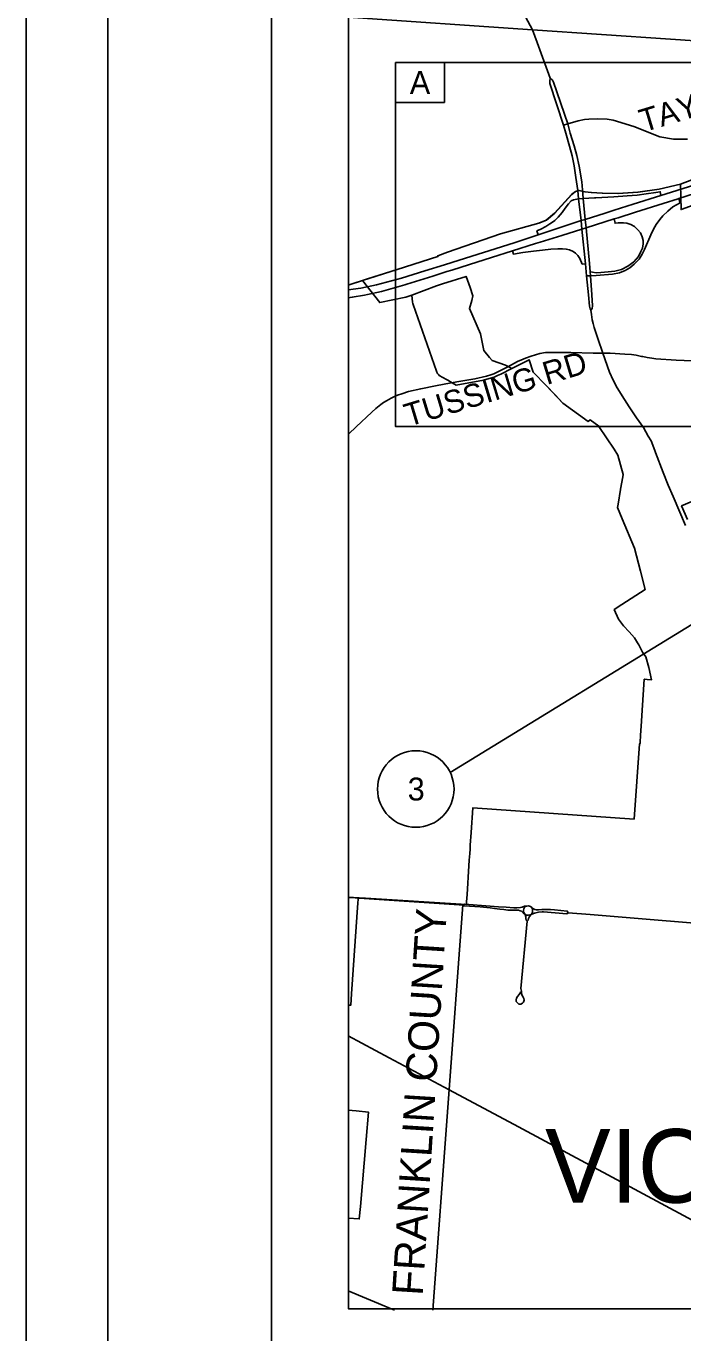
# Model space of a CAD drawing. Extents: x 1880545 to 1948545, y 79309 to 723051.
# Drawn here: x 1880545 to 1888580, y 690858 to 706837 of the extents above; entities that cross this region are included whole.
import ezdxf

# ---------------------------------------------------------------- set-up
doc = ezdxf.new("R2010")
doc.units = 0
for name, color, linetype in [('GM_X_City_Street', 7, 'Continuous'), ('GM_X_Corporation', 7, 'Continuous'), ('GM_X_County', 7, 'Continuous'), ('GM_X_County_Road', 7, 'Continuous'), ('GM_X_County_Text', 7, 'Continuous'), ('GM_X_Interchange_Ramps', 7, 'Continuous'), ('GM_X_Interstate_Route', 7, 'Continuous'), ('GM_X_Rail_Line', 7, 'Continuous'), ('GM_X_State_Route', 7, 'Continuous'), ('GM_X_Township', 7, 'Continuous'), ('GM_X_Township_Road', 7, 'Continuous'), ('GM_X_Township_Text', 7, 'Continuous'), ('SH_Border', 7, 'Continuous'), ('SH_Cut_Line', 7, 'Continuous'), ('SH_Text', 7, 'Continuous')]:
    doc.layers.add(name, color=color, linetype=linetype)

msp = doc.modelspace()

# ---------------------------------------------------------------- linework, layer by layer
at = {"layer": 'GM_X_City_Street'}
for p, q in [((1884485, 696184), (1884503, 696182)), ((1884503, 696182), (1884572, 696178))]:
    msp.add_line(p, q, dxfattribs=at)
for points in [[(1884572, 696178), (1884619, 696174), (1885889, 696091)], [(1886649, 695976), (1886636, 695998), (1886631, 696016), (1886631, 696029), (1886634, 696044), (1886643, 696061), (1886654, 696070), (1886669, 696078)], [(1886723, 695974), (1886735, 695990), (1886739, 696004), (1886742, 696022), (1886740, 696039), (1886733, 696060)], [(1886596, 695027), (1886577, 694995), (1886556, 694972), (1886544, 694952), (1886539, 694932), (1886540, 694911), (1886555, 694892), (1886574, 694879), (1886596, 694879), (1886616, 694888), (1886631, 694903), (1886640, 694925), (1886636, 694945), (1886625, 694963), (1886613, 694985), (1886604, 695009), (1886604, 695037), (1886599, 695070), (1886674, 695891)], [(1886674, 695891), (1886661, 695905), (1886659, 695925), (1886657, 695945), (1886649, 695976)], [(1886674, 695891), (1886687, 695904), (1886693, 695924), (1886704, 695950), (1886723, 695974)]]:
    msp.add_lwpolyline(points, dxfattribs=at)
at = {"layer": 'GM_X_Corporation'}
for points in [[(1889210, 705158), (1888551, 704906), (1888292, 704845), (1888032, 704807), (1887787, 704790), (1887596, 704793), (1887462, 704801), (1887386, 704810), (1887310, 704827), (1887268, 704816), (1887221, 704780), (1887013, 704550), (1886910, 704463), (1886818, 704429), (1886347, 704297), (1885699, 704072), (1885581, 704029), (1885584, 704019), (1885084, 703860), (1884721, 703745), (1884485, 703670)], [(1884485, 694866), (1884517, 694864), (1884527, 695003), (1884605, 696115), (1884607, 696157), (1884609, 696178), (1884697, 696172), (1885931, 696098), (1885932, 696110), (1885934, 696130), (1885940, 696220), (1885944, 696289), (1885949, 696359), (1885953, 696429), (1885958, 696499), (1885962, 696569), (1885967, 696639), (1885972, 696721), (1885976, 696774), (1885979, 696821), (1885989, 696978), (1886009, 697278), (1887984, 697141), (1888050, 698061), (1888055, 698060), (1888056, 698075), (1888056, 698079), (1888062, 698166), (1888074, 698336), (1888074, 698344), (1888108, 698850), (1888108, 698851), (1888109, 698850), (1888145, 698848), (1888194, 698844), (1888195, 698844), (1888195, 698844), (1888162, 698996), (1888126, 699124), (1888088, 699183), (1888040, 699271), (1888024, 699297), (1887987, 699356), (1887921, 699432), (1887852, 699505), (1887794, 699587), (1887740, 699703), (1887833, 699763), (1888117, 699947), (1888060, 700172), (1887989, 700453), (1887837, 700814), (1887780, 700949), (1887787, 700993), (1887818, 701169), (1887818, 701173), (1887845, 701326), (1887850, 701355), (1887785, 701591), (1887738, 701663), (1887551, 701943), (1887551, 701943), (1887550, 701944), (1887444, 702022), (1887422, 702004), (1887112, 702227), (1886909, 702441), (1886750, 702607), (1886700, 702758), (1886673, 702746), (1886495, 702655), (1886487, 702651), (1886459, 702668), (1886442, 702675), (1886408, 702691), (1886327, 702719), (1886247, 702748), (1886215, 702785), (1886143, 702871), (1886106, 703073), (1885968, 703383), (1885997, 703483), (1886012, 703538), (1885978, 703641), (1885927, 703776), (1885641, 703685), (1885565, 703661), (1885264, 703549), (1885190, 703522), (1884872, 703457), (1884660, 703725), (1885084, 703860), (1885584, 704019), (1885581, 704029), (1885699, 704072), (1886347, 704297), (1886818, 704429), (1886907, 704463), (1887011, 704550), (1887219, 704780), (1887265, 704816), (1887308, 704827), (1887384, 704810), (1887460, 704801), (1887594, 704793), (1887785, 704790), (1888030, 704807), (1888290, 704845), (1888551, 704906), (1888559, 704593), (1888998, 704753)], [(1884485, 703670), (1884660, 703725), (1884872, 703457), (1885190, 703522), (1885264, 703549), (1885274, 703460), (1885277, 703447), (1885281, 703433), (1885565, 702619), (1885571, 702604), (1885579, 702590), (1885589, 702577), (1885600, 702566), (1885613, 702556), (1885626, 702547), (1885704, 702506), (1885758, 702477), (1885806, 702445), (1886139, 702509), (1886183, 702519), (1886227, 702531), (1886270, 702546), (1886312, 702563), (1886353, 702582), (1886487, 702651), (1886495, 702655), (1886673, 702746), (1886700, 702758), (1886750, 702607), (1886909, 702441), (1887017, 702328), (1887112, 702227), (1887422, 702004), (1887444, 702022), (1887550, 701944), (1887551, 701943), (1887551, 701943), (1887738, 701663), (1887785, 701591), (1887850, 701355), (1887845, 701326), (1887818, 701173), (1887818, 701169), (1887787, 700993), (1887780, 700949), (1887837, 700814), (1887989, 700453), (1888060, 700172), (1888117, 699947), (1887833, 699763), (1887740, 699703), (1887794, 699587), (1887852, 699505), (1887921, 699432), (1887987, 699356), (1888024, 699297), (1888040, 699271), (1888088, 699183), (1888126, 699124), (1888162, 698996), (1888195, 698844), (1888195, 698844), (1888194, 698844), (1888145, 698848), (1888109, 698850), (1888108, 698851), (1888108, 698850), (1888074, 698344), (1888074, 698336), (1888062, 698166), (1888056, 698079), (1888056, 698075), (1888055, 698060), (1888050, 698061), (1887984, 697141), (1886009, 697278), (1885989, 696978), (1885979, 696821), (1885976, 696774), (1885972, 696721), (1885967, 696639), (1885962, 696569), (1885958, 696499), (1885953, 696429), (1885949, 696359), (1885944, 696289), (1885940, 696220), (1885934, 696130), (1885932, 696110), (1885931, 696098), (1884697, 696172), (1884609, 696178), (1884607, 696157), (1884605, 696115), (1884527, 695003), (1884517, 694864), (1884485, 694866)], [(1888690, 701025), (1888565, 700970), (1888637, 700805)], [(1884485, 692260), (1884621, 692252), (1884634, 692404), (1884706, 693222), (1884735, 693557), (1884581, 693575), (1884485, 693580)], [(1884485, 693580), (1884581, 693575), (1884735, 693557), (1884706, 693222), (1884634, 692404), (1884621, 692252), (1884485, 692260)]]:
    msp.add_lwpolyline(points, dxfattribs=at)
at = {"layer": 'GM_X_County'}
for points in [[(1891843, 720212), (1891817, 719823), (1890200, 719967), (1890150, 719243), (1889940, 716226), (1889896, 715604), (1889789, 714059), (1889789, 714057), (1889728, 713178), (1889728, 713177), (1889680, 712485), (1889677, 712442), (1889513, 710095), (1889456, 709272), (1889272, 706620), (1886741, 706793), (1884485, 706947)], [(1884485, 696186), (1884618, 696177), (1885888, 696093), (1885522, 691136)]]:
    msp.add_lwpolyline(points, dxfattribs=at)
at = {"layer": 'GM_X_County_Road'}
for p, q in [((1884485, 696184), (1884503, 696182)), ((1884503, 696182), (1884572, 696178)), ((1887178, 695996), (1887445, 695974))]:
    msp.add_line(p, q, dxfattribs=at)
for points in [[(1887118, 705624), (1887172, 705641), (1887299, 705679), (1887377, 705694), (1887429, 705699), (1887530, 705705), (1887653, 705699), (1887727, 705686), (1887982, 705610), (1888299, 705483), (1888464, 705456), (1888637, 705456)], [(1884572, 696178), (1884619, 696174), (1885843, 696094), (1885889, 696091)], [(1885889, 696091), (1885908, 696099), (1886223, 696075), (1886326, 696068), (1886418, 696062), (1886513, 696055), (1886550, 696055), (1886592, 696060), (1886615, 696065), (1886643, 696074), (1886669, 696078)], [(1885889, 696091), (1885903, 696082), (1886101, 696068), (1886222, 696056), (1886275, 696049), (1886341, 696040), (1886389, 696034), (1886439, 696029), (1886478, 696027), (1886528, 696027), (1886568, 696026), (1886590, 696021), (1886606, 696013), (1886619, 696003), (1886628, 695995), (1886649, 695976)], [(1886669, 696078), (1886692, 696079), (1886714, 696072), (1886733, 696060)], [(1886733, 696060), (1886746, 696048), (1886767, 696036), (1886787, 696030), (1886812, 696030), (1886853, 696034), (1886905, 696036), (1886960, 696035), (1887008, 696032), (1887166, 696015), (1887178, 695996)], [(1886649, 695976), (1886667, 695968), (1886681, 695967), (1886692, 695967), (1886710, 695969), (1886723, 695974)], [(1886723, 695974), (1886731, 695977), (1886765, 695991), (1886812, 696002), (1886857, 696006), (1886876, 696005), (1887160, 695983), (1887178, 695996)], [(1887445, 695974), (1889359, 695815), (1889579, 695806)], [(1884485, 691372), (1884983, 691165), (1885052, 691136)]]:
    msp.add_lwpolyline(points, dxfattribs=at)
at = {"layer": 'GM_X_Interchange_Ramps'}
for p, q in [((1887360, 704730), (1887305, 704726)), ((1888546, 704676), (1888529, 704729))]:
    msp.add_line(p, q, dxfattribs=at)
for points in [[(1888298, 704810), (1888249, 704802), (1888132, 704786), (1888022, 704771), (1887900, 704761), (1887735, 704750), (1887515, 704737)], [(1888311, 704765), (1888303, 704811), (1888298, 704810)], [(1887305, 704726), (1887284, 704722), (1887243, 704714), (1887214, 704701), (1887179, 704662), (1887141, 704609), (1887102, 704556), (1887054, 704501), (1887012, 704461), (1886959, 704422)], [(1887515, 704737), (1887499, 704736), (1887360, 704730)], [(1887401, 703784), (1887449, 703782), (1887520, 703786), (1887719, 703805), (1887803, 703822), (1887872, 703849), (1887931, 703881), (1887983, 703925), (1888045, 703988), (1888081, 704047), (1888112, 704106), (1888187, 704284), (1888221, 704354), (1888255, 704413), (1888300, 704473), (1888335, 704517), (1888395, 704575), (1888458, 704626), (1888502, 704652), (1888546, 704676)], [(1886959, 704422), (1886954, 704418), (1886902, 704385), (1886841, 704354), (1886795, 704335), (1886809, 704286)], [(1887738, 704479), (1887750, 704427), (1887788, 704432), (1887852, 704432), (1887896, 704426), (1887944, 704412), (1887990, 704385), (1888030, 704346), (1888060, 704308), (1888081, 704261), (1888093, 704217), (1888093, 704173), (1888086, 704122)], [(1886496, 704089), (1886506, 704049), (1886621, 704068), (1886753, 704087), (1886862, 704099), (1886965, 704108), (1887050, 704112), (1887108, 704114), (1887154, 704110), (1887193, 704100), (1887236, 704083), (1887265, 704061), (1887294, 704033), (1887318, 703997), (1887349, 703928), (1887390, 703930)], [(1888086, 704122), (1888066, 704080), (1888036, 704021), (1887981, 703956), (1887908, 703900), (1887829, 703861), (1887747, 703840), (1887665, 703832), (1887577, 703825), (1887518, 703821), (1887475, 703828), (1887445, 703831)]]:
    msp.add_lwpolyline(points, dxfattribs=at)
at = {"layer": 'GM_X_Interstate_Route'}
for points in [[(1888311, 704765), (1888781, 704914), (1889155, 705033), (1889493, 705139), (1889977, 705291), (1890299, 705393), (1890738, 705531), (1891112, 705650), (1891516, 705777), (1891936, 705910), (1892241, 706005), (1892475, 706082), (1892683, 706161), (1892864, 706236), (1893111, 706352)], [(1888524, 704727), (1888529, 704729), (1888724, 704791), (1889017, 704884), (1889477, 705030), (1889979, 705188), (1890285, 705283), (1891077, 705532)], [(1887741, 704586), (1887973, 704660), (1888311, 704765)], [(1887787, 704494), (1888001, 704562), (1888339, 704668), (1888524, 704727)], [(1886778, 704177), (1886835, 704195), (1887099, 704278), (1887344, 704354), (1887396, 704371), (1887738, 704479), (1887787, 704494)], [(1886809, 704286), (1887154, 704401), (1887334, 704459), (1887384, 704474), (1887628, 704551), (1887741, 704586)], [(1884485, 703611), (1884641, 703634), (1884831, 703673), (1885138, 703754), (1885422, 703843), (1885665, 703919), (1885843, 703975), (1886141, 704069), (1886514, 704188), (1886809, 704286)], [(1885204, 703682), (1885521, 703781), (1885693, 703835), (1885753, 703854), (1885970, 703922), (1886238, 704006), (1886496, 704089), (1886778, 704177)], [(1884485, 703516), (1884534, 703522), (1884684, 703548), (1884721, 703555), (1884894, 703591), (1885179, 703674), (1885204, 703682)]]:
    msp.add_lwpolyline(points, dxfattribs=at)
at = {"layer": 'GM_X_Rail_Line'}
for points in [[(1885721, 693829), (1884987, 694223), (1884485, 694491)], [(1890519, 691136), (1890465, 691171), (1889820, 691586), (1889479, 691806), (1889321, 691901), (1888916, 692120), (1886568, 693378), (1885721, 693829)]]:
    msp.add_lwpolyline(points, dxfattribs=at)
at = {"layer": 'GM_X_State_Route'}
msp.add_line((1887293, 704827), (1887305, 704726), dxfattribs=at)
for points in [[(1885372, 708813), (1885438, 708725), (1885820, 708168), (1886304, 707491), (1886624, 707003), (1886742, 706790)], [(1886742, 706790), (1886797, 706638), (1886957, 706199)], [(1886957, 706199), (1886951, 706170), (1886951, 706136), (1887118, 705624)], [(1886957, 706199), (1886983, 706178), (1886998, 706150), (1887172, 705641), (1887203, 705529), (1887252, 705375), (1887284, 705255), (1887311, 705126), (1887343, 704932), (1887351, 704837), (1887360, 704730)], [(1887118, 705624), (1887147, 705527), (1887194, 705369), (1887224, 705251), (1887249, 705130), (1887272, 704988), (1887293, 704827)], [(1887305, 704726), (1887334, 704459), (1887344, 704354), (1887390, 703930), (1887401, 703784)], [(1887360, 704730), (1887384, 704474), (1887396, 704371), (1887438, 703934), (1887445, 703831), (1887449, 703782), (1887466, 703550), (1887474, 703418), (1887469, 703386), (1887455, 703364)], [(1887401, 703784), (1887426, 703551), (1887438, 703411), (1887447, 703382), (1887455, 703364)], [(1887455, 703364), (1887461, 703309), (1887472, 703247), (1887482, 703202), (1887495, 703151), (1887514, 703089), (1887539, 703017), (1887599, 702836)], [(1887599, 702836), (1887692, 702836), (1887868, 702826), (1887950, 702820), (1888008, 702812), (1888074, 702799), (1888091, 702796)], [(1887599, 702836), (1887683, 702605), (1887727, 702506), (1887777, 702415), (1887827, 702336), (1887838, 702318)], [(1888091, 702796), (1888144, 702784), (1888200, 702775), (1888249, 702769), (1888497, 702751), (1888789, 702742), (1888800, 702742)], [(1887838, 702318), (1887925, 702182), (1888013, 702049), (1888098, 701930), (1888157, 701825), (1888191, 701764), (1888237, 701648)], [(1888237, 701648), (1888247, 701623), (1888340, 701380), (1888402, 701223), (1888461, 701085), (1888614, 700732)]]:
    msp.add_lwpolyline(points, dxfattribs=at)
at = {"layer": 'GM_X_Township'}
for points in [[(1886104, 720212), (1886445, 720189), (1890200, 719967), (1890150, 719243), (1889940, 716226), (1889896, 715604), (1889789, 714059), (1889789, 714057), (1889728, 713178), (1889728, 713177), (1889680, 712485), (1889677, 712442), (1889513, 710095), (1889456, 709272), (1889272, 706620), (1886741, 706793), (1884485, 706947)], [(1884485, 706947), (1886741, 706793), (1889272, 706620), (1891302, 706476), (1891974, 706453), (1893110, 706354), (1893307, 706337), (1894183, 706297), (1895332, 706215), (1898403, 705973), (1899947, 705888), (1900524, 705848), (1900988, 705813), (1901285, 705794), (1903803, 705612)], [(1885522, 691136), (1885888, 696093), (1884618, 696177), (1884485, 696186)], [(1884485, 696186), (1884618, 696177), (1885888, 696093), (1885522, 691136)]]:
    msp.add_lwpolyline(points, dxfattribs=at)
at = {"layer": 'GM_X_Township_Road'}
for points in [[(1886484, 702695), (1886557, 702735), (1886625, 702763)], [(1886625, 702763), (1886653, 702775), (1886723, 702801), (1886829, 702832), (1886901, 702846), (1887014, 702846), (1887209, 702845), (1887482, 702838), (1887599, 702836)], [(1885795, 702485), (1885815, 702489), (1886035, 702524), (1886177, 702556), (1886229, 702571), (1886268, 702586), (1886309, 702605), (1886424, 702663), (1886484, 702695)], [(1884485, 701848), (1884492, 701853), (1884583, 701939), (1884774, 702117), (1884823, 702161), (1884884, 702209), (1884917, 702233), (1884952, 702254), (1885010, 702287), (1885051, 702307), (1885090, 702323), (1885140, 702342), (1885225, 702371), (1885372, 702403), (1885555, 702439), (1885745, 702474), (1885795, 702485)]]:
    msp.add_lwpolyline(points, dxfattribs=at)
at = {"layer": 'SH_Border'}
for points in [[(1881545, 722051), (1883545, 722051), (1883545, 680051), (1881545, 680051)], [(1883545, 722051), (1947545, 722051), (1947545, 680051), (1883545, 680051)]]:
    msp.add_lwpolyline(points, close=True, dxfattribs=at)
at = {"layer": 'SH_Cut_Line'}
msp.add_lwpolyline([(1880545, 679051), (1948545, 679051), (1948545, 723051), (1880545, 723051)], close=True, dxfattribs=at)
at = {"layer": 'SH_Text'}
msp.add_line((1885734, 697710), (1889219, 699844), dxfattribs=at)
for points in [[(1884490, 720381), (1928141, 720381), (1928141, 691152), (1884490, 691152)], [(1885063, 706393), (1889914, 706393), (1889914, 701943), (1885063, 701943)]]:
    msp.add_lwpolyline(points, close=True, dxfattribs=at)
msp.add_lwpolyline([(1885063, 705904), (1885663, 705904), (1885663, 706393)], dxfattribs=at)
msp.add_circle((1885312, 697508), 468, dxfattribs=at)

# ---------------------------------------------------------------- texts
at = {"layer": 'GM_X_County_Text'}
msp.add_text('FRANKLIN COUNTY', height=375, rotation=86.3996, dxfattribs=at).set_placement((1885396, 691307))
at = {"layer": 'GM_X_Township_Text'}
msp.add_text('VIOLET', height=900, rotation=0, dxfattribs=at).set_placement((1886894, 692450))
at = {"layer": 'SH_Text'}
for s, p in [('TAYLOR RD SW', (1888098, 705537)), ('TUSSING RD', (1885222, 701937))]:
    msp.add_text(s, height=280, rotation=16.8035, dxfattribs=at).set_placement(p)
for s, p in [('A', (1885239, 706008)), ('3', (1885213, 697368))]:
    msp.add_text(s, height=280, dxfattribs=at).set_placement(p)

doc.saveas('drawing.dxf')
